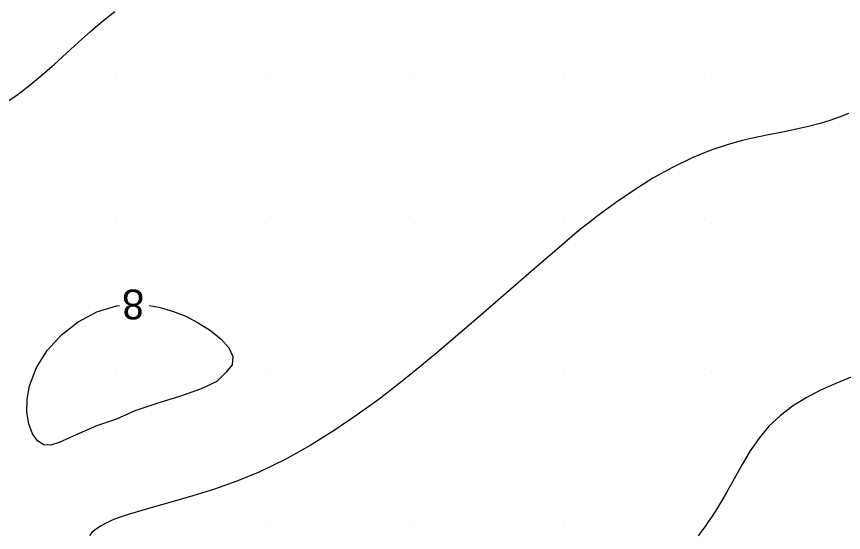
# Model space of a CAD drawing. Extents: x 2602990 to 2605851, y 618069 to 619180.
# Drawn here: x 2603473.3 to 2603528.8, y 618539.2 to 618573.9 of the extents above; entities that cross this region are included whole.
import ezdxf

# ---------------------------------------------------------------- set-up
doc = ezdxf.new("R2010")
doc.units = 0
for name, color, linetype in [('DTM Contours Minor', 7, 'Continuous'), ('DTM Contours Minor Text', 7, 'Continuous'), ('Exist DTM Crownline', 7, 'Continuous'), ('Exist DTM QL2 LIDAR Elevation Point', 7, 'Continuous'), ('Exist Roads EOP', 7, 'Continuous')]:
    doc.layers.add(name, color=color, linetype=linetype)

msp = doc.modelspace()

# ---------------------------------------------------------------- linework, layer by layer
at = {"layer": 'DTM Contours Minor'}
for points in [[(2603472.566, 618568.102), (2603473.394, 618568.666), (2603474.214, 618569.29), (2603475.024, 618569.96), (2603475.845, 618570.68), (2603477.462, 618572.153), (2603478.267, 618572.877), (2603479.075, 618573.571), (2603479.89, 618574.22)], [(2603529.175, 618567.363), (2603528.551, 618567.108), (2603527.912, 618566.885), (2603527.255, 618566.689), (2603526.578, 618566.514), (2603525.88, 618566.355), (2603524.96, 618566.165), (2603524.008, 618565.977), (2603523.029, 618565.775), (2603522.029, 618565.543), (2603521.012, 618565.266), (2603519.985, 618564.929), (2603518.661, 618564.391), (2603517.341, 618563.748), (2603516.037, 618563.019), (2603514.762, 618562.223), (2603513.528, 618561.38), (2603512.347, 618560.51), (2603511.814, 618560.097), (2603511.292, 618559.681), (2603510.777, 618559.261), (2603509.754, 618558.404), (2603508.028, 618556.922), (2603504.291, 618553.676), (2603503.057, 618552.611), (2603501.511, 618551.293), (2603500.492, 618550.443), (2603499.536, 618549.666), (2603498.998, 618549.238), (2603497.639, 618548.193), (2603496.177, 618547.13), (2603494.629, 618546.08), (2603493.01, 618545.074), (2603491.337, 618544.142), (2603489.626, 618543.315), (2603488.1, 618542.691), (2603486.589, 618542.158), (2603485.124, 618541.699), (2603483.737, 618541.3), (2603482.46, 618540.945), (2603481.325, 618540.619), (2603480.799, 618540.454), (2603480.319, 618540.291), (2603479.883, 618540.127), (2603479.632, 618540.022), (2603479.398, 618539.915), (2603479.181, 618539.807), (2603478.981, 618539.697), (2603478.798, 618539.585), (2603478.633, 618539.471), (2603478.38, 618539.262), (2603478.184, 618539.05)], [(2603480, 618546.84), (2603478.74, 618546.422), (2603477.703, 618545.986), (2603476.856, 618545.586), (2603476.165, 618545.273), (2603475.599, 618545.101), (2603475.123, 618545.123), (2603474.702, 618545.387), (2603474.361, 618545.87), (2603474.118, 618546.526), (2603473.991, 618547.312), (2603474, 618548.184), (2603474.162, 618549.098), (2603474.631, 618550.309), (2603475.36, 618551.463), (2603476.306, 618552.508), (2603477.426, 618553.391), (2603478.678, 618554.059), (2603480.018, 618554.46), (2603480.218, 618554.48)], [(2603482.209, 618554.471), (2603482.85, 618554.365), (2603483.773, 618554.104), (2603484.661, 618553.753), (2603485.501, 618553.326), (2603486.331, 618552.799), (2603487.032, 618552.226), (2603487.545, 618551.633), (2603487.813, 618551.048), (2603487.778, 618550.494), (2603487.382, 618550), (2603486.749, 618549.382), (2603485.645, 618548.854), (2603484.245, 618548.376), (2603482.722, 618547.907), (2603481.249, 618547.409), (2603480, 618546.84)], [(2603529.402, 618549.688), (2603528.325, 618549.254), (2603527.294, 618548.789), (2603526.318, 618548.279), (2603525.407, 618547.715), (2603524.57, 618547.083), (2603523.818, 618546.372), (2603523.161, 618545.584), (2603522.571, 618544.724), (2603522.021, 618543.809), (2603520.943, 618541.879), (2603520.362, 618540.896), (2603520.165, 618540.585), (2603519.962, 618540.274), (2603519.751, 618539.963), (2603519.533, 618539.651), (2603519.306, 618539.338), (2603519.069, 618539.024)]]:
    msp.add_lwpolyline(points, dxfattribs=at)
at = {"layer": 'Exist DTM Crownline'}
msp.add_spline([(2603233.488, 618380.754), (2603285.185, 618400.095), (2603335.457, 618418.629), (2603390.812, 618439.069), (2603440.087, 618457.325), (2603493.996, 618477.231), (2603542.655, 618495.301), (2603600.808, 618516.867), (2603653.659, 618536.362), (2603706.222, 618555.742), (2603764.811, 618577.593), (2603823.52, 618599.847), (2603878.564, 618620.56), (2603937.951, 618643.078), (2603997.369, 618665.789), (2604036.209, 618680.665), (2604055.311, 618688.017)], degree=3, dxfattribs=at)
at = {"layer": 'Exist DTM QL2 LIDAR Elevation Point'}
for p, q in [((2603480, 618570), (2603480, 618570)), ((2603490, 618570), (2603490, 618570)), ((2603500, 618570), (2603500, 618570)), ((2603510, 618570), (2603510, 618570)), ((2603520, 618570), (2603520, 618570)), ((2603480, 618560), (2603480, 618560)), ((2603490, 618560), (2603490, 618560)), ((2603500, 618560), (2603500, 618560)), ((2603510, 618560), (2603510, 618560)), ((2603520, 618560), (2603520, 618560)), ((2603480, 618550), (2603480, 618550)), ((2603490, 618550), (2603490, 618550)), ((2603500, 618550), (2603500, 618550)), ((2603510, 618550), (2603510, 618550)), ((2603520, 618550), (2603520, 618550)), ((2603480, 618540), (2603480, 618540)), ((2603490, 618540), (2603490, 618540)), ((2603500, 618540), (2603500, 618540)), ((2603510, 618540), (2603510, 618540)), ((2603520, 618540), (2603520, 618540))]:
    msp.add_line(p, q, dxfattribs=at)
at = {"layer": 'Exist Roads EOP'}
for points in [[(2603230.17, 618389.98), (2603282.929, 618409.597), (2603332.773, 618427.868), (2603388.167, 618448.413), (2603437.203, 618466.721), (2603490.778, 618486.527), (2603539.039, 618504.558), (2603597.451, 618526.156), (2603651.053, 618545.972), (2603705.208, 618566.084), (2603762.02, 618587.183), (2603820.334, 618609.162), (2603876.341, 618629.99), (2603934.909, 618652.28), (2603996.409, 618675.568), (2604033.216, 618689.957), (2604052.01, 618697.199)], [(2604034.633, 618668.486), (2603984.89, 618650.123), (2603936.767, 618631.654), (2603888.195, 618613.335), (2603837.766, 618594.258), (2603782.918, 618573.705), (2603731.939, 618554.39), (2603671.126, 618532.171), (2603621.822, 618514.106), (2603561.545, 618491.877), (2603506.421, 618471.293), (2603452.163, 618451.33), (2603398.364, 618431.316), (2603341.431, 618410.355), (2603281.65, 618388.199), (2603223.033, 618366.475), (2603185.717, 618352.612)]]:
    msp.add_spline(points, degree=3, dxfattribs=at)

# ---------------------------------------------------------------- texts
at = {"layer": 'DTM Contours Minor Text'}
msp.add_text('8', height=2, rotation=179.734, dxfattribs=at).set_placement((2603481.872, 618555.544))

doc.saveas('drawing.dxf')
